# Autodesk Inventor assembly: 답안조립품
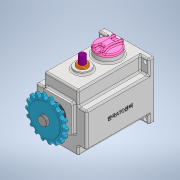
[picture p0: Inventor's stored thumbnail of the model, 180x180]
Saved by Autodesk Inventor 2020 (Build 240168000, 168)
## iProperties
Created: 2022-01
Part Number: 답안조립품
Document SubType Name: Assembly
Designer: user
Author: user
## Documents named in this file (16)
- C:\Users\user\Desktop\답안조립품.iam
- C:\Users\user\Desktop\720112V1003\멈춤나사 M3.ipt
- C:\Users\user\Desktop\720112V1003\메인 축.ipt
- C:\Users\user\Desktop\720112V1003\베어링 608.ipt
- C:\Users\user\Desktop\720112V1003\베어링 6003.ipt
- C:\Users\user\Desktop\720112V1003\볼트 M4 x 10.ipt
- C:\Users\user\Desktop\720112V1003\부시.ipt
- C:\Users\user\Desktop\720112V1003\상부 캡.ipt
- C:\Users\user\Desktop\720112V1003\서브 축.ipt
- C:\Users\user\Desktop\720112V1003\스프로킷.ipt
- C:\Users\user\Desktop\720112V1003\슬라이더.ipt
- C:\Users\user\Desktop\720112V1003\오일 실 8 x 22 x 7.ipt
- C:\Users\user\Desktop\720112V1003\오일 실 17 x 32 x 8.ipt
- C:\Users\user\Desktop\720112V1003\커버.ipt
- C:\Users\user\Desktop\720112V1003\키 5 x 5.ipt
- C:\Users\user\Desktop\본체.ipt
